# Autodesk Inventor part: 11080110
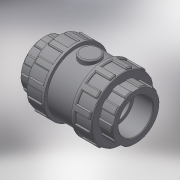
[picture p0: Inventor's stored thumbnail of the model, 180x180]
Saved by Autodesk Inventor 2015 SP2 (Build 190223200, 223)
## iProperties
Created: 2017-11
Part Number: 11080110
Material: Generic
Description: PLASSON CHECK VALVE CEM 110 PTFE COATED SPRING + EPDM O-RING
Document SubType Name: Modeling
Designer: KIM
Density: 1 g/cm^3
Appearance: Default
Author: KIM
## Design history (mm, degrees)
derived "110800 - 110600 110900-110000.ipt"
feature "Solid1::110800 - 110600 110900-110000.ipt"
tag "TaggingFeature1"
body "Solid1"
other parameters: "d0" = 295, "d2" = 207, "d3" = 61, "d4" = 88, "d5" = 42.7, "d7" = 154, "d8" = 186.3, "d13" = 3.3, "d23" = 61, "d24" = 198.72, "d25" = 2.2, "d26" = 3.3, "d27" = 31.05, "d28" = 15.525, "d29" = 45.75, "d30" = 0, "d35" = 3.3, "d39" = 103.5, "d45" = 360 deg, "d47" = 2.2, "d50" = 103.5, "d51" = 62.1, "d53" = 0, "d54" = 4.14, "d55" = 22, "d56" = 11, "d57" = 42.7, "d58" = 0, "d59" = 3.3, "d61" = 360 deg, "l_" = 61, "H_" = 295, "K_" = 207
